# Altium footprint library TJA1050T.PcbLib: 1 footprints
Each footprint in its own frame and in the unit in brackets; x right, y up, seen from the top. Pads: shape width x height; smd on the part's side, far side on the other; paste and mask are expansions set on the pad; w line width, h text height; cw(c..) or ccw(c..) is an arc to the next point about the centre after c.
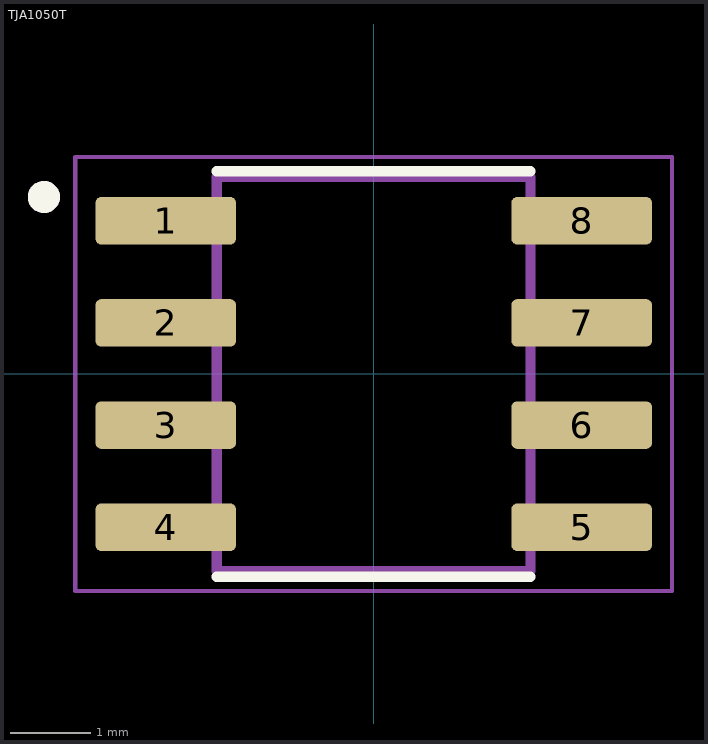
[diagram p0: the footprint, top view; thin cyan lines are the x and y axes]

## TJA1050T [mm]
pads (8):
  rrect25% 1.75x0.59 smd: 1(-2.585,1.905) 2(-2.585,0.635) 3(-2.585,-0.635) 4(-2.585,-1.905) 5(2.585,-1.905) 6(2.585,-0.635) 7(2.585,0.635) 8(2.585,1.905)
Top Overlay:
  circle w0.2: c-4.1,2.2 r0.1
  lines w0.127: -1.95,-2.52 1.95,-2.52 ; -1.95,2.52 1.95,2.52
Mechanical 13:
  circle w0.2: c-4.1,2.2 r0.1
  lines w0.127: -1.95,-2.45 1.95,-2.45 1.95,2.45 -1.95,2.45 -1.95,-2.45
Mechanical 15:
  lines w0.05: -3.71,-2.7 3.71,-2.7 3.71,2.7 -3.71,2.7 -3.71,-2.7
3D body "step_temp.STEP": height 1.75, standoff 0, extent -3,-2.45 3,2.45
